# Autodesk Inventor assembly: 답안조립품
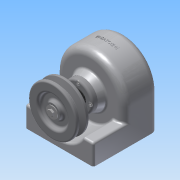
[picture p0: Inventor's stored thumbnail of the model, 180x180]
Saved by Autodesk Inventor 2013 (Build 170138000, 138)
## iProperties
Created: 2015-02
Part Number: 답안조립품
Document SubType Name: Assembly
Designer: Administrator
Author: Administrator
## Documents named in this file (14)
- C:\Documents and Settings\Administrator\바탕 화면\450214V1022\답안조립품.iam
- C:\Documents and Settings\Administrator\바탕 화면\450214V1022\1-본체.ipt
- C:\Documents and Settings\Administrator\바탕 화면\450214V1022\베어링 6001.ipt
- C:\Documents and Settings\Administrator\바탕 화면\450214V1022\축.ipt
- C:\Documents and Settings\Administrator\바탕 화면\450214V1022\5-스퍼기어.ipt
- C:\Documents and Settings\Administrator\바탕 화면\450214V1022\키5x5.ipt
- C:\Documents and Settings\Administrator\바탕 화면\450214V1022\오일실.ipt
- C:\Documents and Settings\Administrator\바탕 화면\450214V1022\축커버.ipt
- C:\Documents and Settings\Administrator\바탕 화면\450214V1022\M3x0.5.ipt
- C:\Documents and Settings\Administrator\바탕 화면\450214V1022\4-V-벨트풀리.ipt
- C:\Documents and Settings\Administrator\바탕 화면\450214V1022\와샤.ipt
- C:\Documents and Settings\Administrator\바탕 화면\450214V1022\키4x4.ipt
- C:\Documents and Settings\Administrator\바탕 화면\450214V1022\M5x0.8.ipt
- M5x0.8.ipt
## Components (7 placed, 4 different names)
1. 1-본체:1
2. 4-V-벨트풀리:1 — 각도:4
3. M5x0.8:1
4. M3x0.5:1
5. M3x0.5:2
6. M3x0.5:3
7. M3x0.5:4
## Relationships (1: Angle 1)
- 각도:4 [Angle]: 4-V-벨트풀리:1
